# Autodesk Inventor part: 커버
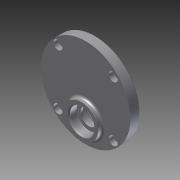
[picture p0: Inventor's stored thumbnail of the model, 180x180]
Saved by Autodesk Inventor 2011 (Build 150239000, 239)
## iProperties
Created: 2014-12
Part Number: 커버
Document SubType Name: Modeling
Designer: Administrator
Density: 1 g/cm^3
Author: Administrator
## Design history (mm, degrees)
sketch "스케치1"
  geometry: C1 r 40 at (0, 0); 1 further point
  constraints: 1 centre point, 1 coincident
  dimensions: "d0" = 80 diameter of C1
extrude "돌출1" new body sketch "스케치1" distance "d1" = 9; taper "d2" = 0 deg
sketch "스케치2"
  geometry: C1 r 40 at (0, 0) reference; C2 r 15 at (0, -20)
  constraints: 1 centre point, 1 vertical alignment
  dimensions: "d3" = 30 diameter of C2; "d4" = 20 distance of C1.centre C2.centre
extrude "돌출2" join sketch "스케치2" distance "d5" = 4; taper "d6" = 0 deg
sketch "스케치3"
  geometry: C1 r 40 at (0, 0) reference; C2 r 14 at (0, 11); C3 r 14 at (0, -20)
  constraints: 2 centre point, 2 vertical alignment
  dimensions: "d7" = 28 diameter of C2; "d8" = 28 diameter of C3; "d9" = 11 distance of C2.centre C1.centre; "d10" = 20 distance of C3.centre C1.centre
extrude "돌출3" join sketch "스케치3" distance "d11" = 3; taper "d12" = 0 deg
sketch "스케치4"
  geometry: C1 r 14 at (0, 0) reference; C2 r 11 at (0, 0); C3 r 14 at (0, -31) reference; C4 r 11 at (0, -31); 1 further point
  constraints: 2 centre point, 2 coincident
  dimensions: "d13" = 22 diameter of C2; "d14" = 22 diameter of C4
extrude "돌출4" cut sketch "스케치4" distance "d15" = 7; taper "d16" = 0 deg
sketch "스케치5"
  geometry: C1 r 9 at (0, 0); 2 further points
  constraints: 1 centre point, 1 coincident, 1 vertical alignment
  dimensions: "d17" = 18 diameter of C1
extrude "돌출5" cut sketch "스케치5" distance "d18" = 1; taper "d19" = 0 deg
sketch "스케치6"
  geometry: C1 r 11 at (0, 0) reference; C2 r 7.5 at (0, 0); 1 further point
  constraints: 1 centre point, 1 coincident
  dimensions: "d20" = 15 diameter of C2
extrude "돌출6" cut sketch "스케치6" distance "d21" = 2; taper "d22" = 0 deg
sketch "스케치7"
  geometry: C1 r 15 at (0, 0) reference; C2 r 11 at (0, 0); 1 further point
  constraints: 1 centre point, 1 coincident
  dimensions: "d23" = 22 diameter of C2
extrude "돌출7" cut sketch "스케치7" distance "d24" = 7; taper "d25" = 0 deg
sketch "스케치8" dims "d26" = 70
  geometry: L1 (0, 0)-(24.749, 24.749); L2 (0, 0)-(35, 0); C1 r 40 at (0, 0) reference; 1 further point
  constraints: 4 end point, 2 coincident, 1 equal length, 1 horizontal, 3 other
  dimensions: "d27" = 45 deg angle of L2 L1
hole "Hole1" sketch "스케치8" at (24.749, 24.749) diameter "d28" = 4.5; stored, may be unused: countersink angle "d32" = 90 deg, drill point angle "d34" = 118 deg; dims "d29" = 6, "d30" = 8, "d31" = 4.4, "d33" = 8
chamfer "모따기1" distance "d38" = 1; stored, may be unused: second distance "d39" = 2, angle "d40" = 45 deg
fillet "모깎기1" dims "d41" = 2, "d42" = 0.3
node "솔리드1"
pattern_circular "원형 패턴1" dims angle "d36" = 360 deg
node "투영된 루프1"
